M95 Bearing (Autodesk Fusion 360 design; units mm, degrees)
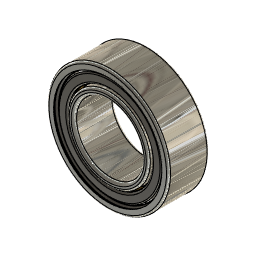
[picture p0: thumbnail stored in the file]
sketch "Sketch1" plane through (0, 0, 0) normal (1, 0, 0) x axis (0, 1, 0)
  line L1 (1.5, 0) -> (-1.5, 0)
  line L2 (-1.5, 4.5) -> (-1.5, 2.5)
  line L3 (1.5, 4.5) -> (-1.5, 4.5)
  line L4 (1.5, 2.5) -> (1.5, 4.5)
  line L5 (1.5, 2.5) -> (-1.5, 2.5)
  line L6 (0.7332, 3.93) -> (-0.7332, 3.93)
  line L7 (0.7332, 3.07) -> (-0.7332, 3.07)
  line L8 (1.5, 3.5) -> (-1.5, 3.5)
  line L9 (0, 2.5) -> (0, 4.5)
  line L10 (-1.2497, 3.1744) -> (-1.15, 3.15)
  line L11 (-1.3069, 3.7266) -> (-1.3069, 3.2473)
  line L12 (-1.1819, 3.8723) -> (-1.282, 3.7823)
  line L13 (-1.2465, 4.1302) -> (-1.1646, 3.9608)
  line L14 (-1.4015, 4.1198) -> (-1.3642, 4.1533)
  line L15 (-1.4263, 4.02) -> (-1.4263, 4.064)
  line L16 (-1.2615, 3.1261) -> (-1.1618, 3.1017)
  line L17 (-1.3566, 3.7266) -> (-1.3566, 3.2473)
  line L18 (-1.2152, 3.9093) -> (-1.3153, 3.8193)
  line L19 (-1.2913, 4.1085) -> (-1.2093, 3.9391)
  line L20 (-1.3682, 4.0828) -> (-1.3309, 4.1163)
  line L21 (-1.3766, 4.02) -> (-1.3766, 4.064)
  line L22 (-1.2286, 4.1389) -> (-1.1614, 4)
  line L23 (-1.4148, 4.1347) -> (-1.3776, 4.1682)
  line L24 (-1.4463, 4) -> (-1.4463, 4.064)
  line L25 (-1.4463, 4) -> (-1.5036, 4)
  line L26 (-1.3766, 4.02) -> (-1.4263, 4.02)
  line L27 (-1.1618, 3.1017) -> (-1.15, 3.15)
  line L28 (-0.559, 4) -> (-1.1614, 4)
  line L29 (-0.559, 3) -> (-1.5, 3)
  line L30 (1.5, 3) -> (0.559, 3)
  line L31 (1.4463, 4) -> (1.5036, 4)
  line L32 (1.1618, 3.1017) -> (1.15, 3.15)
  line L33 (1.2152, 3.9093) -> (1.3153, 3.8193)
  line L34 (1.3766, 4.02) -> (1.4263, 4.02)
  line L35 (1.4148, 4.1347) -> (1.3776, 4.1682)
  line L36 (1.3566, 3.7266) -> (1.3566, 3.2473)
  line L37 (1.2286, 4.1389) -> (1.1614, 4)
  line L38 (1.3069, 3.7266) -> (1.3069, 3.2473)
  line L39 (1.2615, 3.1261) -> (1.1618, 3.1017)
  line L40 (1.2497, 3.1744) -> (1.15, 3.15)
  line L41 (1.4463, 4) -> (1.4463, 4.064)
  line L42 (1.4263, 4.02) -> (1.4263, 4.064)
  line L43 (1.2913, 4.1085) -> (1.2093, 3.9391)
  line L44 (1.4015, 4.1198) -> (1.3642, 4.1533)
  line L45 (1.3766, 4.02) -> (1.3766, 4.064)
  line L46 (1.1819, 3.8723) -> (1.282, 3.7823)
  line L47 (1.2465, 4.1302) -> (1.1646, 3.9608)
  line L48 (1.3682, 4.0828) -> (1.3309, 4.1163)
  line L49 (0.559, 4) -> (1.1614, 4)
  circle C1 centre (0, 3.5) radius 0.75
  arc A1 centre (-1.3141, 4.0975) radius 0.075 clockwise from (-1.3642, 4.1533) to (-1.2465, 4.1302)
  arc A2 centre (-1.3513, 4.064) radius 0.075 clockwise from (-1.4263, 4.064) to (-1.4015, 4.1198)
  arc A3 centre (-1.2321, 3.9281) radius 0.075 clockwise from (-1.1646, 3.9608) to (-1.1819, 3.8723)
  arc A4 centre (-1.2319, 3.7266) radius 0.075 clockwise from (-1.3069, 3.7266) to (-1.282, 3.7823)
  arc A5 centre (-1.2319, 3.2473) radius 0.075 clockwise from (-1.2497, 3.1744) to (-1.3069, 3.2473)
  arc A6 centre (-1.2319, 3.2473) radius 0.1247 clockwise from (-1.2615, 3.1261) to (-1.3566, 3.2473)
  arc A7 centre (-1.2319, 3.7266) radius 0.1247 clockwise from (-1.3566, 3.7266) to (-1.3153, 3.8193)
  arc A8 centre (-1.2321, 3.9281) radius 0.0253 clockwise from (-1.2093, 3.9391) to (-1.2152, 3.9093)
  arc A9 centre (-1.3141, 4.0975) radius 0.0253 clockwise from (-1.3309, 4.1163) to (-1.2913, 4.1085)
  arc A10 centre (-1.3513, 4.064) radius 0.0253 clockwise from (-1.3766, 4.064) to (-1.3682, 4.0828)
  arc A11 centre (-1.3141, 4.0975) radius 0.095 clockwise from (-1.3776, 4.1682) to (-1.2286, 4.1389)
  arc A12 centre (-1.3513, 4.064) radius 0.095 clockwise from (-1.4463, 4.064) to (-1.4148, 4.1347)
  arc A13 centre (0, 3.5) radius 0.85 clockwise from (0.7332, 3.93) to (0.7332, 3.07)
  arc A14 centre (0, 3.5) radius 0.85 clockwise from (-0.7332, 3.07) to (-0.7332, 3.93)
  arc A15 centre (1.2319, 3.7266) radius 0.1247 clockwise from (1.3153, 3.8193) to (1.3566, 3.7266)
  arc A16 centre (1.3513, 4.064) radius 0.095 clockwise from (1.4148, 4.1347) to (1.4463, 4.064)
  arc A17 centre (1.2321, 3.9281) radius 0.0253 clockwise from (1.2152, 3.9093) to (1.2093, 3.9391)
  arc A18 centre (1.3141, 4.0975) radius 0.075 clockwise from (1.2465, 4.1302) to (1.3642, 4.1533)
  arc A19 centre (1.2319, 3.7266) radius 0.075 clockwise from (1.282, 3.7823) to (1.3069, 3.7266)
  arc A20 centre (1.3513, 4.064) radius 0.075 clockwise from (1.4015, 4.1198) to (1.4263, 4.064)
  arc A21 centre (1.2321, 3.9281) radius 0.075 clockwise from (1.1819, 3.8723) to (1.1646, 3.9608)
  arc A22 centre (1.3141, 4.0975) radius 0.0253 clockwise from (1.2913, 4.1085) to (1.3309, 4.1163)
  arc A23 centre (1.2319, 3.2473) radius 0.075 clockwise from (1.3069, 3.2473) to (1.2497, 3.1744)
  arc A24 centre (1.2319, 3.2473) radius 0.1247 clockwise from (1.3566, 3.2473) to (1.2615, 3.1261)
  arc A25 centre (1.3141, 4.0975) radius 0.095 clockwise from (1.2286, 4.1389) to (1.3776, 4.1682)
  arc A26 centre (1.3513, 4.064) radius 0.0253 clockwise from (1.3682, 4.0828) to (1.3766, 4.064)
  point P1 (0, 0)
  point P7 (-1.5, 3)
  point P8 (1.5, 3)
  point P15 (0.7332, 3.07)
  point P2 (-1.5, 0)
  point P9 (-1.5, 2.5)
  point P3 (1.5, 0)
  point P10 (1.5, 2.5)
  point P16 (-1.5, 3.5)
  point P17 (1.5, 3.5)
  point P6 (0, 3.5)
  point P18 (0, 4.5)
  point P19 (0, 2.5)
  point P64 (-0.559, 4)
  point P65 (0.559, 3)
  point P66 (-0.559, 3)
  point P86 (1.5, 3.5)
  point P20 (-1.15, 3.15)
  point P97 (1.15, 3.15)
  point P21 (-1.4263, 4.02)
  point P95 (1.4263, 4.02)
  point P22 (-1.2465, 4.1302)
  point P99 (1.2465, 4.1302)
  point P23 (-1.3642, 4.1533)
  point P96 (1.3642, 4.1533)
  point P25 (-1.4015, 4.1198)
  point P98 (1.4015, 4.1198)
  point P26 (-1.4263, 4.064)
  point P87 (1.4263, 4.064)
  point P28 (-1.1819, 3.8723)
  point P88 (1.1819, 3.8723)
  point P29 (-1.1646, 3.9608)
  point P93 (1.1646, 3.9608)
  point P31 (-1.3069, 3.7266)
  point P92 (1.3069, 3.7266)
  point P32 (-1.282, 3.7823)
  point P91 (1.282, 3.7823)
  point P34 (-1.2497, 3.1744)
  point P90 (1.2497, 3.1744)
  point P35 (-1.3069, 3.2473)
  point P89 (1.3069, 3.2473)
  point P37 (-1.1618, 3.1017)
  point P94 (1.1618, 3.1017)
  point P38 (-1.2615, 3.1261)
  point P83 (1.2615, 3.1261)
  point P40 (-1.3566, 3.2473)
  point P81 (1.3566, 3.2473)
  point P41 (-1.3566, 3.7266)
  point P80 (1.3566, 3.7266)
  point P43 (-1.3153, 3.8193)
  point P84 (1.3153, 3.8193)
  point P44 (-1.2152, 3.9093)
  point P79 (1.2152, 3.9093)
  point P46 (-1.2093, 3.9391)
  point P85 (1.2093, 3.9391)
  point P47 (-1.2913, 4.1085)
  point P82 (1.2913, 4.1085)
  point P49 (-1.3309, 4.1163)
  point P71 (1.3309, 4.1163)
  point P50 (-1.3682, 4.0828)
  point P76 (1.3682, 4.0828)
  point P52 (-1.3766, 4.064)
  point P75 (1.3766, 4.064)
  point P53 (-1.3766, 4.02)
  point P77 (1.3766, 4.02)
  point P54 (-1.2286, 4.1389)
  point P78 (1.2286, 4.1389)
  point P56 (-1.3776, 4.1682)
  point P72 (1.3776, 4.1682)
  point P57 (-1.4148, 4.1347)
  point P106 (1.4148, 4.1347)
  point P59 (-1.4463, 4.064)
  point P109 (1.4463, 4.064)
  point P60 (-1.4463, 4)
  point P101 (1.4463, 4)
  point P61 (-1.1614, 4)
  point P102 (1.1614, 4)
  point P62 (-1.5036, 4)
  point P104 (1.5036, 4)
  point P111 (0.559, 4)
  horizontal L1
  midpoint P1 L1
  perpendicular L1 L2
  perpendicular L2 L3
  perpendicular L1 L4
  coincident L2 P7
  coincident L4 P8
  perpendicular L4 L29
  perpendicular L4 L5
  concentric C1 A14
  perpendicular L2 L6
  coincident P15 A14
  parallel L7 L29
  equal L6 L7
  vertical P2 P9
  vertical P3 P10
  midpoint L2 P16
  midpoint L4 P17
  midpoint P6 L8
  midpoint L3 P18
  midpoint L5 P19
  vertical L11
  parallel L12 L14
  tangent L13 A1
  tangent L14 A1
  tangent L14 A2
  tangent L15 A2
  equal A1 A2
  tangent L12 A3
  tangent L13 A3
  equal A1 A3
  tangent L11 A4
  tangent L12 A4
  equal A1 A4
  tangent L10 A5
  tangent L11 A5
  equal A1 A5
  parallel L13 L22
  concentric A1 A11
  parallel L14 L23
  concentric A2 A12
  parallel L15 L24
  tangent L22 A11
  tangent A11 L23
  tangent L23 A12
  tangent A12 L24
  collinear L25 L28
  perpendicular L15 L26
  concentric A13 A14
  coincident C1 P64
  coincident C1 P65
  collinear L29 L30
  coincident C1 P66
  symmetric P16 L9 P86
  symmetric L9 P20 P97
  symmetric L9 P21 P95
  symmetric L9 P22 P99
  symmetric L9 P23 P96
  symmetric L9 A1 A18
  symmetric L9 P25 P98
  symmetric L9 P26 P87
  symmetric L9 A2 A20
  symmetric L9 P28 P88
  symmetric L9 P29 P93
  symmetric L9 A3 A21
  symmetric L9 P31 P92
  symmetric L9 P32 P91
  symmetric L9 A4 A19
  symmetric L9 P34 P90
  symmetric L9 P35 P89
  symmetric L9 A5 A23
  symmetric L9 P37 P94
  symmetric L9 P38 P83
  symmetric L9 P40 P81
  symmetric L9 A6 A24
  symmetric L9 P41 P80
  symmetric L9 P43 P84
  symmetric L9 A7 A15
  symmetric L9 P44 P79
  symmetric L9 P46 P85
  symmetric L9 A8 A17
  symmetric L9 P47 P82
  symmetric L9 P49 P71
  symmetric L9 A9 A22
  symmetric L9 P50 P76
  symmetric L9 P52 P75
  symmetric L9 A10 A26
  symmetric L9 P53 P77
  symmetric L9 P54 P78
  symmetric L9 P56 P72
  symmetric L9 A11 A25
  symmetric L9 P57 P106
  symmetric L9 P59 P109
  symmetric L9 A12 A16
  symmetric L9 P60 P101
  symmetric L9 P61 P102
  symmetric L9 P62 P104
  symmetric L9 P64 P111
  dimension "d1" distance L1 L5 = 2.5
  dimension "d2" distance L1 L3 = 4.5
  dimension "d3" distance P2 P3 = 3
  dimension "d4" diameter C1 = 1.5
  dimension "d5" distance C1 A14 = 0.1
  dimension "d7" distance L5 L29 = 0.5
  dimension "d9" radius A1 = 0.075
  dimension "d10" = -0.0497
canvas "Canvas1"
revolve "Revolve1" sketch "Sketch1" AlongAngle 360
sphere_primitive "SpherePrimitive1" Diameter 1.5
sphere_primitive "SpherePrimitive2" Diameter 1.45
circular_pattern "C-Pattern1" countU 12 TotalAngle 360
fillet "Fillet1" radius 0.15
fillet "Fillet3" radius 0.2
